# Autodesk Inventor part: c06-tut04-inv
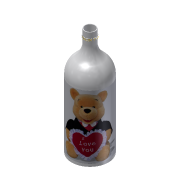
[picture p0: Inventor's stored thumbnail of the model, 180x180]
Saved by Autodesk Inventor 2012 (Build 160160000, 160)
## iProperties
Created: 2010-03
Part Number: c06-tut04-inv
Document SubType Name: Modeling
Designer: CADSoft
Density: 1 g/cm^3
Material: Default
Author: CADSoft
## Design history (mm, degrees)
sketch "Sketch1"
  geometry: 1 further point
sketch "Sketch2"
  geometry: L1 (0, 0)-(30, 0); L2 (30, 0)-(30, 113.567); L3 (8, 160)-(8, 180); L4 (0, -1)-(31, -1); L5 (31, -1)-(31, 113.567); L6 (9, 160)-(9, 180); L7 (9, 180)-(8, 180); L8 (0, 0)-(0, -1); L9 (0, -37.2)-(0, 216.2) reference; A1 r 30 centre (0, 113.567) between (30, 113.567) and (19, 136.784); A2 r 30 centre (38, 160) between (8, 160) and (19, 136.784); A3 r 31 centre (0, 113.567) between (31, 113.567) and (19.633, 137.558); A4 r 29 centre (38, 160) between (9, 160) and (19.633, 137.558)
  constraints: 16 end point, 8 point on circle, 4 centre point, 3 tangent, 2 vertical, 1 horizontal, 4 other
  dimensions: "d0" = 30 distance of L1.start L1.end; "d1" = 180 vertical distance of L1.end L3.end; "d2" = 30 radius of A1; "d3" = 30 radius of A2; "d4" = 20 distance of L3.start L3.end; "d7" = 8 distance from line of A1.centre L3; "d8" = 1 distance between parallel lines of L3 L6
revolve "Revolution1" sketch "Sketch2" stored, may be unused: angle "d9" = 90 deg
workplane "Work Plane1"
sketch "Sketch3"
  geometry: L1 (-21.993, 114.823)-(26.045, 114.823); L2 (26.045, 114.823)-(26.045, 111.018); L3 (26.045, 111.018)-(-21.993, 111.018); L4 (-21.993, 111.018)-(-21.993, 114.823); 1 further point
  constraints: 2 other
emboss "Emboss1" sketch "Sketch3" dims "d1" = 180, "d10" = 1, "d11" = 0
sketch "Sketch4"
  geometry: L1 (-79.426, 53.84)-(72.133, 53.84); L2 (72.133, 53.84)-(72.133, -52.9); L3 (72.133, -52.9)-(-79.426, -52.9); L4 (-79.426, -52.9)-(-79.426, 53.84); 1 further point; 1 other entity
  constraints: 2 other
feature "Decal1" sketch "Sketch4"
body "Solid1"
node "Image1"
